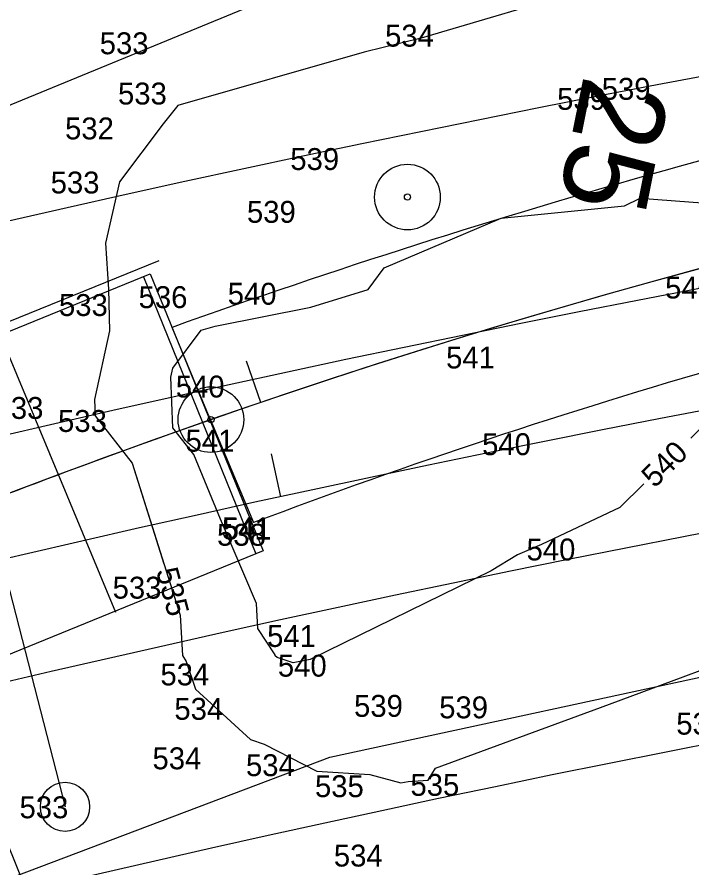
# Model space of a CAD drawing. Extents: x 1787461 to 1970323, y 938412 to 1118748.
# Drawn here: x 1967860.3 to 1967921.9, y 1117863.4 to 1117941.2 of the extents above; entities that cross this region are included whole.
import ezdxf

# ---------------------------------------------------------------- set-up
doc = ezdxf.new("R2010")
doc.units = 0
for name, color, linetype in [('Default', 7, 'Continuous'), ('HHA ADDITIONAL XSs', 7, 'Continuous'), ('Level 19', 7, 'Continuous'), ('RD_EX_Bridge', 7, 'Continuous'), ('RD_EX_DV_Prop', 7, 'Continuous'), ('RD_EX_Misc', 7, 'Continuous'), ('RD_EX_Road', 7, 'Continuous'), ('RD_EX_VEG', 7, 'Continuous'), ('RD_HC_CL', 7, 'Continuous'), ('RD_HC_CL_Rel', 7, 'Continuous'), ('RD_HC_Data', 7, 'Continuous'), ('RD_HC_Data_Tic', 7, 'Continuous'), ('RD_HC_Data_Tic_Rel', 7, 'Continuous'), ('RD_HC_TX_Sta50', 7, 'Continuous'), ('RD_PD_Final_TrvlWay', 7, 'Continuous'), ('RD_SMD_Locator', 7, 'Continuous')]:
    doc.layers.add(name, color=color, linetype=linetype)

msp = doc.modelspace()

# ---------------------------------------------------------------- linework, layer by layer
at = {"layer": 'Default'}
for points in [[(1967994.282, 1117971.647), (1967981.705, 1117970.254), (1967967.128, 1117977.046), (1967948.495, 1117955.921), (1967957.825, 1117949.659), (1967958.427, 1117949.202), (1967947.149, 1117946.051), (1967943.563, 1117945.988), (1967931.774, 1117945.421), (1967929.141, 1117945.374), (1967913.023, 1117943.936), (1967912.711, 1117943.859), (1967897.205, 1117939.273), (1967891.983, 1117937.995), (1967874.97, 1117933.116), (1967873.603, 1117931.424), (1967869.613, 1117926.132), (1967868.343, 1117920.541), (1967868.615, 1117916.322), (1967868.718, 1117912.519), (1967867.342, 1117906.253), (1967867.404, 1117904.753), (1967870.794, 1117900.42), (1967873.686, 1117891.227)], [(1967994.282, 1117971.647), (1967981.705, 1117970.254), (1967967.128, 1117977.046), (1967948.495, 1117955.921), (1967957.825, 1117949.659), (1967958.427, 1117949.202), (1967947.149, 1117946.051), (1967943.563, 1117945.988), (1967931.774, 1117945.421), (1967929.141, 1117945.374), (1967913.023, 1117943.936), (1967912.711, 1117943.859), (1967897.205, 1117939.273), (1967891.983, 1117937.995), (1967874.97, 1117933.116), (1967873.603, 1117931.424), (1967869.613, 1117926.132), (1967868.343, 1117920.541), (1967868.615, 1117916.322), (1967868.718, 1117912.519), (1967867.342, 1117906.253), (1967867.404, 1117904.753), (1967870.794, 1117900.42), (1967873.686, 1117891.227)], [(1967994.282, 1117971.647), (1967981.705, 1117970.254), (1967967.128, 1117977.046), (1967948.495, 1117955.921), (1967957.825, 1117949.659), (1967958.427, 1117949.202), (1967947.149, 1117946.051), (1967943.563, 1117945.988), (1967931.774, 1117945.421), (1967929.141, 1117945.374), (1967913.023, 1117943.936), (1967912.711, 1117943.859), (1967897.205, 1117939.273), (1967891.983, 1117937.995), (1967874.97, 1117933.116), (1967873.603, 1117931.424), (1967869.613, 1117926.132), (1967868.343, 1117920.541), (1967868.615, 1117916.322), (1967868.718, 1117912.519), (1967867.342, 1117906.253), (1967867.404, 1117904.753), (1967870.794, 1117900.42), (1967873.686, 1117891.227)], [(1967994.282, 1117971.647), (1967981.705, 1117970.254), (1967967.128, 1117977.046), (1967948.495, 1117955.921), (1967957.825, 1117949.659), (1967958.427, 1117949.202), (1967947.149, 1117946.051), (1967943.563, 1117945.988), (1967931.774, 1117945.421), (1967929.141, 1117945.374), (1967913.023, 1117943.936), (1967912.711, 1117943.859), (1967897.205, 1117939.273), (1967891.983, 1117937.995), (1967874.97, 1117933.116), (1967873.603, 1117931.424), (1967869.613, 1117926.132), (1967868.343, 1117920.541), (1967868.615, 1117916.322), (1967868.718, 1117912.519), (1967867.342, 1117906.253), (1967867.404, 1117904.753), (1967870.794, 1117900.42), (1967873.686, 1117891.227)], [(1967994.282, 1117971.647), (1967981.705, 1117970.254), (1967967.128, 1117977.046), (1967948.495, 1117955.921), (1967957.825, 1117949.659), (1967958.427, 1117949.202), (1967947.149, 1117946.051), (1967943.563, 1117945.988), (1967931.774, 1117945.421), (1967929.141, 1117945.374), (1967913.023, 1117943.936), (1967912.711, 1117943.859), (1967897.205, 1117939.273), (1967891.983, 1117937.995), (1967874.97, 1117933.116), (1967873.603, 1117931.424), (1967869.613, 1117926.132), (1967868.343, 1117920.541), (1967868.615, 1117916.322), (1967868.718, 1117912.519), (1967867.342, 1117906.253), (1967867.404, 1117904.753), (1967870.794, 1117900.42), (1967873.686, 1117891.227)], [(1967994.282, 1117971.647), (1967981.705, 1117970.254), (1967967.128, 1117977.046), (1967948.495, 1117955.921), (1967957.825, 1117949.659), (1967958.427, 1117949.202), (1967947.149, 1117946.051), (1967943.563, 1117945.988), (1967931.774, 1117945.421), (1967929.141, 1117945.374), (1967913.023, 1117943.936), (1967912.711, 1117943.859), (1967897.205, 1117939.273), (1967891.983, 1117937.995), (1967874.97, 1117933.116), (1967873.603, 1117931.424), (1967869.613, 1117926.132), (1967868.343, 1117920.541), (1967868.615, 1117916.322), (1967868.718, 1117912.519), (1967867.342, 1117906.253), (1967867.404, 1117904.753), (1967870.794, 1117900.42), (1967873.686, 1117891.227)], [(1967912.711, 1117943.859), (1967897.205, 1117939.273), (1967891.983, 1117937.995), (1967874.97, 1117933.116), (1967873.603, 1117931.424), (1967869.613, 1117926.132), (1967868.343, 1117920.541), (1967868.615, 1117916.322), (1967868.718, 1117912.519), (1967867.342, 1117906.253), (1967867.404, 1117904.753), (1967870.794, 1117900.42), (1967875.16, 1117886.543), (1967875.367, 1117882.838), (1967875.72, 1117882.292), (1967876.566, 1117879.776), (1967881.612, 1117875.163), (1967882.855, 1117874.74), (1967887.674, 1117872.28), (1967892.496, 1117871.973), (1967895.346, 1117871.22), (1967895.997, 1117871.333), (1967897.822, 1117871.466), (1967898.509, 1117872.552), (1967913.602, 1117878.093), (1967921.151, 1117880.908), (1967924.74, 1117882.232)], [(1967874.314, 1117908.289), (1967874.49, 1117909.091), (1967877.089, 1117912.572), (1967878.377, 1117912.946), (1967887.101, 1117914.691), (1967892.341, 1117916.297), (1967893.814, 1117918.289), (1967904.508, 1117922.8), (1967915.796, 1117923.925), (1967917.206, 1117924.638), (1967926.116, 1117923.982), (1967941.12, 1117922.762), (1967939.879, 1117920.897), (1967933.976, 1117912.447), (1967923.556, 1117904.409), (1967921.832, 1117902.72)], [(1967874.314, 1117908.289), (1967874.49, 1117909.091), (1967877.089, 1117912.572), (1967878.377, 1117912.946), (1967887.101, 1117914.691), (1967892.341, 1117916.297), (1967893.814, 1117918.289), (1967904.508, 1117922.8), (1967915.796, 1117923.925), (1967917.206, 1117924.638), (1967926.116, 1117923.982), (1967941.12, 1117922.762), (1967939.879, 1117920.897), (1967933.976, 1117912.447), (1967923.556, 1117904.409), (1967921.832, 1117902.72)], [(1967874.314, 1117908.289), (1967874.49, 1117909.091), (1967877.089, 1117912.572), (1967878.377, 1117912.946), (1967887.101, 1117914.691), (1967892.341, 1117916.297), (1967893.814, 1117918.289), (1967904.508, 1117922.8), (1967915.796, 1117923.925), (1967917.206, 1117924.638), (1967926.116, 1117923.982), (1967941.12, 1117922.762), (1967939.879, 1117920.897), (1967933.976, 1117912.447), (1967923.556, 1117904.409), (1967921.832, 1117902.72)], [(1967874.314, 1117908.289), (1967874.49, 1117909.091), (1967877.089, 1117912.572), (1967878.377, 1117912.946), (1967887.101, 1117914.691), (1967892.341, 1117916.297), (1967893.814, 1117918.289), (1967904.508, 1117922.8), (1967915.796, 1117923.925), (1967917.206, 1117924.638), (1967926.116, 1117923.982), (1967941.12, 1117922.762), (1967939.879, 1117920.897), (1967933.976, 1117912.447), (1967923.556, 1117904.409), (1967921.832, 1117902.72)], [(1967874.314, 1117908.289), (1967874.49, 1117909.091), (1967877.089, 1117912.572), (1967878.377, 1117912.946), (1967887.101, 1117914.691), (1967892.341, 1117916.297), (1967893.814, 1117918.289), (1967904.508, 1117922.8), (1967915.796, 1117923.925), (1967917.206, 1117924.638), (1967926.116, 1117923.982), (1967941.12, 1117922.762), (1967939.879, 1117920.897), (1967933.976, 1117912.447), (1967923.556, 1117904.409), (1967921.832, 1117902.72)], [(1967874.314, 1117908.289), (1967874.49, 1117909.091), (1967877.089, 1117912.572), (1967878.377, 1117912.946), (1967887.101, 1117914.691), (1967892.341, 1117916.297), (1967893.814, 1117918.289), (1967904.508, 1117922.8), (1967915.796, 1117923.925), (1967917.206, 1117924.638), (1967926.116, 1117923.982), (1967941.12, 1117922.762), (1967939.879, 1117920.897), (1967933.976, 1117912.447), (1967923.556, 1117904.409), (1967921.832, 1117902.72)], [(1967874.314, 1117908.289), (1967874.49, 1117909.091), (1967877.089, 1117912.572), (1967878.377, 1117912.946), (1967887.101, 1117914.691), (1967892.341, 1117916.297), (1967893.814, 1117918.289), (1967904.508, 1117922.8), (1967915.796, 1117923.925), (1967917.206, 1117924.638), (1967926.116, 1117923.982), (1967941.12, 1117922.762), (1967939.879, 1117920.897), (1967933.976, 1117912.447), (1967923.556, 1117904.409), (1967921.832, 1117902.72)], [(1967917.547, 1117898.521), (1967915.362, 1117896.381), (1967908.208, 1117892.995), (1967906.003, 1117892.046), (1967903.584, 1117890.595), (1967887.046, 1117882.472), (1967885.512, 1117882.172), (1967884.022, 1117882.678), (1967883.866, 1117882.82), (1967883.84, 1117882.898), (1967882.271, 1117885.327), (1967882.144, 1117887.593), (1967878.865, 1117895.31), (1967876.418, 1117901.211), (1967874.505, 1117903.655), (1967874.314, 1117908.289)], [(1967917.547, 1117898.521), (1967915.362, 1117896.381), (1967908.208, 1117892.995), (1967906.003, 1117892.046), (1967903.584, 1117890.595), (1967887.046, 1117882.472), (1967885.512, 1117882.172), (1967884.022, 1117882.678), (1967883.866, 1117882.82), (1967883.84, 1117882.898), (1967882.271, 1117885.327), (1967882.144, 1117887.593), (1967878.865, 1117895.31), (1967876.418, 1117901.211), (1967874.505, 1117903.655), (1967874.314, 1117908.289)], [(1967917.547, 1117898.521), (1967915.362, 1117896.381), (1967908.208, 1117892.995), (1967906.003, 1117892.046), (1967903.584, 1117890.595), (1967887.046, 1117882.472), (1967885.512, 1117882.172), (1967884.022, 1117882.678), (1967883.866, 1117882.82), (1967883.84, 1117882.898), (1967882.271, 1117885.327), (1967882.144, 1117887.593), (1967878.865, 1117895.31), (1967876.418, 1117901.211), (1967874.505, 1117903.655), (1967874.314, 1117908.289)], [(1967917.547, 1117898.521), (1967915.362, 1117896.381), (1967908.208, 1117892.995), (1967906.003, 1117892.046), (1967903.584, 1117890.595), (1967887.046, 1117882.472), (1967885.512, 1117882.172), (1967884.022, 1117882.678), (1967883.866, 1117882.82), (1967883.84, 1117882.898), (1967882.271, 1117885.327), (1967882.144, 1117887.593), (1967878.865, 1117895.31), (1967876.418, 1117901.211), (1967874.505, 1117903.655), (1967874.314, 1117908.289)], [(1967917.547, 1117898.521), (1967915.362, 1117896.381), (1967908.208, 1117892.995), (1967906.003, 1117892.046), (1967903.584, 1117890.595), (1967887.046, 1117882.472), (1967885.512, 1117882.172), (1967884.022, 1117882.678), (1967883.866, 1117882.82), (1967883.84, 1117882.898), (1967882.271, 1117885.327), (1967882.144, 1117887.593), (1967878.865, 1117895.31), (1967876.418, 1117901.211), (1967874.505, 1117903.655), (1967874.314, 1117908.289)], [(1967917.547, 1117898.521), (1967915.362, 1117896.381), (1967908.208, 1117892.995), (1967906.003, 1117892.046), (1967903.584, 1117890.595), (1967887.046, 1117882.472), (1967885.512, 1117882.172), (1967884.022, 1117882.678), (1967883.866, 1117882.82), (1967883.84, 1117882.898), (1967882.271, 1117885.327), (1967882.144, 1117887.593), (1967878.865, 1117895.31), (1967876.418, 1117901.211), (1967874.505, 1117903.655), (1967874.314, 1117908.289)], [(1967917.547, 1117898.521), (1967915.362, 1117896.381), (1967908.208, 1117892.995), (1967906.003, 1117892.046), (1967903.584, 1117890.595), (1967887.046, 1117882.472), (1967885.512, 1117882.172), (1967884.022, 1117882.678), (1967883.866, 1117882.82), (1967883.84, 1117882.898), (1967882.271, 1117885.327), (1967882.144, 1117887.593), (1967878.865, 1117895.31), (1967876.418, 1117901.211), (1967874.505, 1117903.655), (1967874.314, 1117908.289)], [(1967875.221, 1117885.455), (1967875.367, 1117882.838), (1967875.72, 1117882.292), (1967876.566, 1117879.776), (1967881.612, 1117875.163), (1967882.855, 1117874.74), (1967887.674, 1117872.28), (1967892.496, 1117871.973), (1967895.346, 1117871.22), (1967895.997, 1117871.333), (1967897.822, 1117871.466), (1967898.509, 1117872.552), (1967913.602, 1117878.093), (1967921.151, 1117880.908), (1967924.74, 1117882.232)], [(1967875.221, 1117885.455), (1967875.367, 1117882.838), (1967875.72, 1117882.292), (1967876.566, 1117879.776), (1967881.612, 1117875.163), (1967882.855, 1117874.74), (1967887.674, 1117872.28), (1967892.496, 1117871.973), (1967895.346, 1117871.22), (1967895.997, 1117871.333), (1967897.822, 1117871.466), (1967898.509, 1117872.552), (1967913.602, 1117878.093), (1967921.151, 1117880.908), (1967924.74, 1117882.232)], [(1967875.221, 1117885.455), (1967875.367, 1117882.838), (1967875.72, 1117882.292), (1967876.566, 1117879.776), (1967881.612, 1117875.163), (1967882.855, 1117874.74), (1967887.674, 1117872.28), (1967892.496, 1117871.973), (1967895.346, 1117871.22), (1967895.997, 1117871.333), (1967897.822, 1117871.466), (1967898.509, 1117872.552), (1967913.602, 1117878.093), (1967921.151, 1117880.908), (1967924.74, 1117882.232)], [(1967875.221, 1117885.455), (1967875.367, 1117882.838), (1967875.72, 1117882.292), (1967876.566, 1117879.776), (1967881.612, 1117875.163), (1967882.855, 1117874.74), (1967887.674, 1117872.28), (1967892.496, 1117871.973), (1967895.346, 1117871.22), (1967895.997, 1117871.333), (1967897.822, 1117871.466), (1967898.509, 1117872.552), (1967913.602, 1117878.093), (1967921.151, 1117880.908), (1967924.74, 1117882.232)], [(1967875.221, 1117885.455), (1967875.367, 1117882.838), (1967875.72, 1117882.292), (1967876.566, 1117879.776), (1967881.612, 1117875.163), (1967882.855, 1117874.74), (1967887.674, 1117872.28), (1967892.496, 1117871.973), (1967895.346, 1117871.22), (1967895.997, 1117871.333), (1967897.822, 1117871.466), (1967898.509, 1117872.552), (1967913.602, 1117878.093), (1967921.151, 1117880.908), (1967924.74, 1117882.232)], [(1967875.221, 1117885.455), (1967875.367, 1117882.838), (1967875.72, 1117882.292), (1967876.566, 1117879.776), (1967881.612, 1117875.163), (1967882.855, 1117874.74), (1967887.674, 1117872.28), (1967892.496, 1117871.973), (1967895.346, 1117871.22), (1967895.997, 1117871.333), (1967897.822, 1117871.466), (1967898.509, 1117872.552), (1967913.602, 1117878.093), (1967921.151, 1117880.908), (1967924.74, 1117882.232)]]:
    msp.add_lwpolyline(points, dxfattribs=at)
at = {"layer": 'HHA ADDITIONAL XSs'}
for radius in [1667.022, 1607.022]:
    msp.add_arc((1968231.344, 1116297.536), radius, 87.726628, 111.995838, dxfattribs=at)
at = {"layer": 'Level 19'}
msp.add_line((1967857.67, 1117896.136), (1967864.643, 1117869.018), dxfattribs=at)
msp.add_circle((1967864.643, 1117869.018), 2.25, dxfattribs=at)
at = {"layer": 'RD_EX_Bridge'}
msp.add_lwpolyline([(1967691.931, 1117844.089), (1967872.418, 1117917.737), (1967882.757, 1117892.409), (1967702.27, 1117818.76), (1967691.931, 1117844.089)], dxfattribs=at)
at = {"layer": 'RD_EX_DV_Prop'}
for start, end in [(87.726629, 109.21172), (109.21172, 111.995834)]:
    msp.add_arc((1968093.163, 1117286.891), 653.927, start, end, dxfattribs=at)
at = {"layer": 'RD_EX_Misc'}
for p, q in [((1967691.117, 1117844.933), (1967873.24, 1117918.941)), ((1967871.811, 1117917.437), (1967882.093, 1117892.124)), ((1967858.768, 1117912.008), (1967869.264, 1117886.806))]:
    msp.add_line(p, q, dxfattribs=at)
at = {"layer": 'RD_EX_Road'}
for points in [[(1967877.753, 1117904.821), (1967874.432, 1117912.835)], [(1967877.753, 1117904.821), (1967881.886, 1117894.989)]]:
    msp.add_lwpolyline(points, dxfattribs=at)
for centre, radius, start, end in [((1968103.685, 1117270.425), 682.091, 101.716237, 109.639617), ((1968079.391, 1117372.324), 558.737, 101.3479, 110.70062)]:
    msp.add_arc(centre, radius, start, end, dxfattribs=at)
at = {"layer": 'RD_EX_VEG'}
for points in [[(1967420.801, 1117819.076), (1967452.151, 1117758.283), (1967558.571, 1117805.529), (1967843.242, 1117926.429), (1967916.628, 1117956.613), (1968008.442, 1117968.2), (1968060.252, 1117967.439), (1968104.576, 1117972.693), (1968157.629, 1117966.15), (1968211.146, 1117963.438), (1968421.934, 1117955.987), (1968535.191, 1117951.616)], [(1967302.31, 1117610.369), (1967337.759, 1117649.577), (1967352.047, 1117663.921), (1967393.533, 1117676.593), (1967483.377, 1117717.021), (1967710.354, 1117806.032), (1967888.861, 1117873.573), (1967928.064, 1117882.041), (1967957.92, 1117887.348), (1967975.7, 1117893.862), (1968013.091, 1117903.708), (1968102.912, 1117899.224), (1968154.077, 1117904.837), (1968208.625, 1117905.242), (1968319.32, 1117902.869), (1968421.81, 1117901.579), (1968527.925, 1117886.313)]]:
    msp.add_lwpolyline(points, dxfattribs=at)
at = {"layer": 'RD_HC_CL'}
msp.add_arc((1968093.163, 1117286.891), 653.927, 87.726628, 111.995838, dxfattribs=at)
at = {"layer": 'RD_HC_CL_Rel'}
msp.add_arc((1968231.344, 1116297.536), 1637.022, 87.726628, 111.995838, dxfattribs=at)
at = {"layer": 'RD_HC_Data'}
msp.add_line((1967848.241, 1117893.219), (1967891.709, 1117785.612), dxfattribs=at)
for centre, radius in [((1967895.944, 1117924.741), 3), ((1967895.944, 1117924.741), 0.282), ((1967877.982, 1117904.4), 3), ((1967877.982, 1117904.4), 0.282)]:
    msp.add_circle(centre, radius, dxfattribs=at)
at = {"layer": 'RD_HC_Data_Tic'}
msp.add_line((1967882.53, 1117905.966), (1967881.242, 1117909.753), dxfattribs=at)
at = {"layer": 'RD_HC_Data_Tic_Rel'}
msp.add_line((1967884.355, 1117897.361), (1967883.508, 1117901.27), dxfattribs=at)
at = {"layer": 'RD_PD_Final_TrvlWay'}
for radius in [1648.022, 1626.022]:
    msp.add_arc((1968231.344, 1116297.536), radius, 87.726628, 111.995838, dxfattribs=at)
at = {"layer": 'RD_SMD_Locator'}
for centre in [(1967895.944, 1117924.741), (1967877.982, 1117904.4)]:
    msp.add_circle(centre, 0.001, dxfattribs=at)

# ---------------------------------------------------------------- texts
at = {"layer": 'Default'}
for s, p in [('534', (1967893.899, 1117938.488)), ('533', (1967867.814, 1117937.793)), ('533', (1967869.487, 1117933.2)), ('539', (1967913.701, 1117933.63)), ('539', (1967909.622, 1117932.711)), ('532', (1967864.65, 1117930.013)), ('539', (1967885.235, 1117927.215)), ('533', (1967863.332, 1117925.07)), ('539', (1967881.272, 1117922.391)), ('540', (1967919.491, 1117915.471)), ('536', (1967871.371, 1117914.595)), ('540', (1967879.514, 1117914.906)), ('533', (1967864.091, 1117913.873)), ('541', (1967899.475, 1117909.08)), ('540', (1967874.768, 1117906.422)), ('533', (1967858.207, 1117904.469)), ('533', (1967864.005, 1117903.278)), ('541', (1967875.66, 1117901.477)), ('540', (1967902.766, 1117901.157)), ('541', (1967878.982, 1117893.462)), ('541', (1967879.054, 1117893.448)), ('538', (1967878.536, 1117892.88)), ('540', (1967906.828, 1117891.536)), ('533', (1967868.995, 1117888.046)), ('541', (1967883.115, 1117883.631)), ('540', (1967884.098, 1117880.917)), ('534', (1967873.367, 1117880.117)), ('539', (1967891.063, 1117877.245)), ('539', (1967898.844, 1117877.109)), ('534', (1967874.638, 1117876.972)), ('533', (1967920.511, 1117875.618)), ('534', (1967872.639, 1117872.451)), ('534', (1967881.182, 1117871.823)), ('535', (1967887.491, 1117869.904)), ('535', (1967896.216, 1117870.024)), ('533', (1967860.486, 1117867.976)), ('534', (1967889.216, 1117863.562))]:
    msp.add_text(s, height=2, dxfattribs=at).set_placement(p)
for s, rotation, p in [('540', 44.41459, (1967918.528, 1117898.083)), ('540', 44.41459, (1967918.528, 1117898.083)), ('540', 44.41459, (1967918.528, 1117898.083)), ('540', 44.41459, (1967918.528, 1117898.083)), ('540', 44.41459, (1967918.528, 1117898.083)), ('540', 44.41459, (1967918.528, 1117898.083)), ('540', 44.41459, (1967918.528, 1117898.083)), ('535', 284.88675, (1967872.959, 1117890.596)), ('535', 284.88675, (1967872.959, 1117890.596)), ('535', 284.88675, (1967872.959, 1117890.596)), ('535', 284.88675, (1967872.959, 1117890.596)), ('535', 284.88675, (1967872.959, 1117890.596)), ('535', 284.88675, (1967872.959, 1117890.596))]:
    msp.add_text(s, height=2, rotation=rotation, dxfattribs=at).set_placement(p)
at = {"layer": 'RD_HC_TX_Sta50'}
msp.add_text('25', height=8, rotation=258.61042, dxfattribs=at).set_placement((1967912.099, 1117936.03))

doc.saveas('drawing.dxf')
